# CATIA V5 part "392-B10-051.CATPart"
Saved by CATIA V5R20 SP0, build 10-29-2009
Part number: 392-B10-051
Definition: NONE
Nomenclature: 392-B10-051
Source: Unknown
Description: 392-B10-051
Bounding box of the stored display mesh (mm): x 0 to 51, y -4.695 to 4.695, z -4.65 to 4.65
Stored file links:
  C:\Users\Utente\Desktop\IO LAVORO\3D X SITO CF\X SITO\3D files 392B\392-B10-051.CATPart
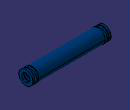
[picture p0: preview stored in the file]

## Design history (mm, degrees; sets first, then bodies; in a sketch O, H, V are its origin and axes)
Body1 "392-B10-051" (main body)
  Solid1: solid without history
